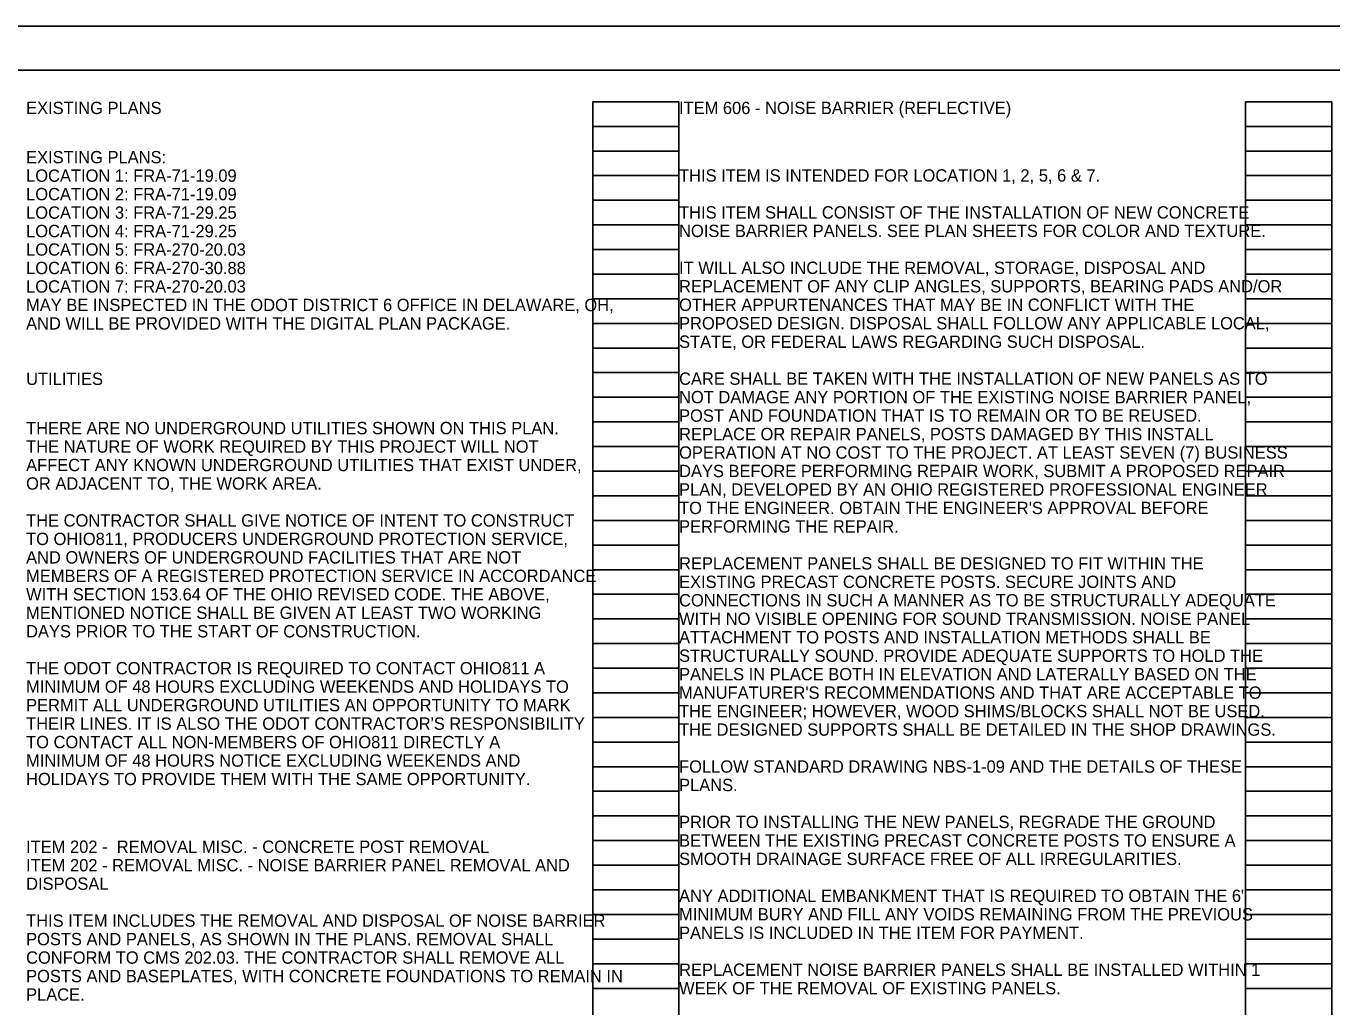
# Model space of a CAD drawing. Extents: x -10.6 to 34, y -3 to 22.
# Drawn here: x 9.82 to 24.66, y 10.85 to 22 of the extents above; entities that cross this region are included whole.
import ezdxf

# ---------------------------------------------------------------- set-up
doc = ezdxf.new("R2010")
doc.units = 0
for name, color, linetype in [('SH_Border', 7, 'Continuous'), ('SH_Cut_Line', 7, 'Continuous'), ('SH_Data', 7, 'Continuous'), ('SH_Text', 7, 'Continuous')]:
    doc.layers.add(name, color=color, linetype=linetype)

msp = doc.modelspace()

# ---------------------------------------------------------------- linework, layer by layer
at = {"layer": 'SH_Border'}
msp.add_lwpolyline([(1.5, 21.5), (33.5, 21.5), (33.5, 0.5), (1.5, 0.5)], close=True, dxfattribs=at)
at = {"layer": 'SH_Cut_Line'}
msp.add_lwpolyline([(0, 0), (34, 0), (34, 22), (0, 22)], close=True, dxfattribs=at)
at = {"layer": 'SH_Data'}
for p, q in [((16.26, 0.98), (16.26, 21.14)), ((16.26, 21.14), (17.24, 21.14)), ((17.24, 0.98), (17.24, 21.14)), ((23.68, 0.98), (23.68, 21.14)), ((23.68, 21.14), (24.66, 21.14)), ((24.66, 0.98), (24.66, 21.14)), ((16.26, 20.86), (17.24, 20.86)), ((23.68, 20.86), (24.66, 20.86)), ((16.26, 20.58), (17.24, 20.58)), ((23.68, 20.58), (24.66, 20.58)), ((16.26, 20.3), (17.24, 20.3)), ((23.68, 20.3), (24.66, 20.3)), ((16.26, 20.02), (17.24, 20.02)), ((23.68, 20.02), (24.66, 20.02)), ((16.26, 19.74), (17.24, 19.74)), ((23.68, 19.74), (24.66, 19.74)), ((16.26, 19.46), (17.24, 19.46)), ((23.68, 19.46), (24.66, 19.46)), ((16.26, 19.18), (17.24, 19.18)), ((23.68, 19.18), (24.66, 19.18)), ((16.26, 18.9), (17.24, 18.9)), ((23.68, 18.9), (24.66, 18.9)), ((16.26, 18.62), (17.24, 18.62)), ((23.68, 18.62), (24.66, 18.62)), ((16.26, 18.34), (17.24, 18.34)), ((23.68, 18.34), (24.66, 18.34)), ((16.26, 18.06), (17.24, 18.06)), ((23.68, 18.06), (24.66, 18.06)), ((16.26, 17.78), (17.24, 17.78)), ((23.68, 17.78), (24.66, 17.78)), ((16.26, 17.5), (17.24, 17.5)), ((23.68, 17.5), (24.66, 17.5)), ((16.26, 17.22), (17.24, 17.22)), ((23.68, 17.22), (24.66, 17.22)), ((16.26, 16.94), (17.24, 16.94)), ((23.68, 16.94), (24.66, 16.94)), ((16.26, 16.66), (17.24, 16.66)), ((23.68, 16.66), (24.66, 16.66)), ((16.26, 16.38), (17.24, 16.38)), ((23.68, 16.38), (24.66, 16.38)), ((16.26, 16.1), (17.24, 16.1)), ((23.68, 16.1), (24.66, 16.1)), ((16.26, 15.82), (17.24, 15.82)), ((23.68, 15.82), (24.66, 15.82)), ((16.26, 15.54), (17.24, 15.54)), ((23.68, 15.54), (24.66, 15.54)), ((16.26, 15.26), (17.24, 15.26)), ((23.68, 15.26), (24.66, 15.26)), ((16.26, 14.98), (17.24, 14.98)), ((23.68, 14.98), (24.66, 14.98)), ((16.26, 14.7), (17.24, 14.7)), ((23.68, 14.7), (24.66, 14.7)), ((16.26, 14.42), (17.24, 14.42)), ((23.68, 14.42), (24.66, 14.42)), ((16.26, 14.14), (17.24, 14.14)), ((23.68, 14.14), (24.66, 14.14)), ((16.26, 13.86), (17.24, 13.86)), ((23.68, 13.86), (24.66, 13.86)), ((16.26, 13.58), (17.24, 13.58)), ((23.68, 13.58), (24.66, 13.58)), ((16.26, 13.3), (17.24, 13.3)), ((23.68, 13.3), (24.66, 13.3)), ((16.26, 13.02), (17.24, 13.02)), ((23.68, 13.02), (24.66, 13.02)), ((16.26, 12.74), (17.24, 12.74)), ((23.68, 12.74), (24.66, 12.74)), ((16.26, 12.46), (17.24, 12.46)), ((23.68, 12.46), (24.66, 12.46)), ((16.26, 12.18), (17.24, 12.18)), ((23.68, 12.18), (24.66, 12.18)), ((16.26, 11.9), (17.24, 11.9)), ((23.68, 11.9), (24.66, 11.9)), ((16.26, 11.62), (17.24, 11.62)), ((23.68, 11.62), (24.66, 11.62)), ((16.26, 11.34), (17.24, 11.34)), ((23.68, 11.34), (24.66, 11.34)), ((16.26, 11.06), (17.24, 11.06)), ((23.68, 11.06), (24.66, 11.06))]:
    msp.add_line(p, q, dxfattribs=at)

# ---------------------------------------------------------------- texts
at = {"layer": 'SH_Text'}
for s, p in [('EXISTING PLANS', (9.82, 21)), ('ITEM 606 - NOISE BARRIER (REFLECTIVE)', (17.24, 21)), ('EXISTING PLANS:', (9.82, 20.44)), ('LOCATION 1: FRA-71-19.09', (9.82, 20.23)), ('THIS ITEM IS INTENDED FOR LOCATION 1, 2, 5, 6 & 7.', (17.241, 20.232)), ('LOCATION 2: FRA-71-19.09', (9.82, 20.02)), ('LOCATION 3: FRA-71-29.25', (9.82, 19.81)), ('THIS ITEM SHALL CONSIST OF THE INSTALLATION OF NEW CONCRETE ', (17.241, 19.812)), ('LOCATION 4: FRA-71-29.25', (9.82, 19.6)), ('NOISE BARRIER PANELS. SEE PLAN SHEETS FOR COLOR AND TEXTURE.', (17.241, 19.602)), ('LOCATION 5: FRA-270-20.03', (9.82, 19.39)), ('LOCATION 6: FRA-270-30.88', (9.82, 19.18)), ('IT WILL ALSO INCLUDE THE REMOVAL, STORAGE, DISPOSAL AND ', (17.241, 19.182)), ('LOCATION 7: FRA-270-20.03', (9.82, 18.97)), ('REPLACEMENT OF ANY CLIP ANGLES, SUPPORTS, BEARING PADS AND/OR ', (17.241, 18.972)), ('MAY BE INSPECTED IN THE ODOT DISTRICT 6 OFFICE IN DELAWARE, OH, ', (9.82, 18.76)), ('OTHER APPURTENANCES THAT MAY BE IN CONFLICT WITH THE ', (17.241, 18.762)), ('AND WILL BE PROVIDED WITH THE DIGITAL PLAN PACKAGE.', (9.82, 18.55)), ('PROPOSED DESIGN. DISPOSAL SHALL FOLLOW ANY APPLICABLE LOCAL, ', (17.241, 18.552)), ('STATE, OR FEDERAL LAWS REGARDING SUCH DISPOSAL.', (17.241, 18.342)), ('UTILITIES', (9.82, 17.92)), ('CARE SHALL BE TAKEN WITH THE INSTALLATION OF NEW PANELS AS TO ', (17.241, 17.922)), ('NOT DAMAGE ANY PORTION OF THE EXISTING NOISE BARRIER PANEL, ', (17.241, 17.712)), ('POST AND FOUNDATION THAT IS TO REMAIN OR TO BE REUSED. ', (17.241, 17.502)), ('THERE ARE NO UNDERGROUND UTILITIES SHOWN ON THIS PLAN. ', (9.82, 17.36)), ('REPLACE OR REPAIR PANELS, POSTS DAMAGED BY THIS INSTALL ', (17.241, 17.292)), ('THE NATURE OF WORK REQUIRED BY THIS PROJECT WILL NOT ', (9.82, 17.15)), ('OPERATION AT NO COST TO THE PROJECT. AT LEAST SEVEN (7) BUSINESS ', (17.241, 17.082)), ('AFFECT ANY KNOWN UNDERGROUND UTILITIES THAT EXIST UNDER, ', (9.82, 16.94)), ('DAYS BEFORE PERFORMING REPAIR WORK, SUBMIT A PROPOSED REPAIR ', (17.241, 16.872)), ('OR ADJACENT TO, THE WORK AREA.', (9.82, 16.73)), ('PLAN, DEVELOPED BY AN OHIO REGISTERED PROFESSIONAL ENGINEER ', (17.241, 16.662)), ("TO THE ENGINEER. OBTAIN THE ENGINEER'S APPROVAL BEFORE ", (17.241, 16.452)), ('THE CONTRACTOR SHALL GIVE NOTICE OF INTENT TO CONSTRUCT ', (9.82, 16.31)), ('PERFORMING THE REPAIR.', (17.241, 16.242)), ('TO OHIO811, PRODUCERS UNDERGROUND PROTECTION SERVICE, ', (9.82, 16.1)), ('AND OWNERS OF UNDERGROUND FACILITIES THAT ARE NOT ', (9.82, 15.89)), ('REPLACEMENT PANELS SHALL BE DESIGNED TO FIT WITHIN THE ', (17.241, 15.822)), ('MEMBERS OF A REGISTERED PROTECTION SERVICE IN ACCORDANCE ', (9.82, 15.68)), ('EXISTING PRECAST CONCRETE POSTS. SECURE JOINTS AND ', (17.241, 15.612)), ('WITH SECTION 153.64 OF THE OHIO REVISED CODE. THE ABOVE, ', (9.82, 15.47)), ('CONNECTIONS IN SUCH A MANNER AS TO BE STRUCTURALLY ADEQUATE ', (17.241, 15.402)), ('MENTIONED NOTICE SHALL BE GIVEN AT LEAST TWO WORKING ', (9.82, 15.26)), ('WITH NO VISIBLE OPENING FOR SOUND TRANSMISSION. NOISE PANEL ', (17.241, 15.192)), ('DAYS PRIOR TO THE START OF CONSTRUCTION.', (9.82, 15.05)), ('ATTACHMENT TO POSTS AND INSTALLATION METHODS SHALL BE ', (17.241, 14.982)), ('STRUCTURALLY SOUND. PROVIDE ADEQUATE SUPPORTS TO HOLD THE ', (17.241, 14.772)), ('THE ODOT CONTRACTOR IS REQUIRED TO CONTACT OHIO811 A ', (9.82, 14.63)), ('PANELS IN PLACE BOTH IN ELEVATION AND LATERALLY BASED ON THE ', (17.241, 14.562)), ('MINIMUM OF 48 HOURS EXCLUDING WEEKENDS AND HOLIDAYS TO ', (9.82, 14.42)), ("MANUFATURER'S RECOMMENDATIONS AND THAT ARE ACCEPTABLE TO ", (17.241, 14.352)), ('PERMIT ALL UNDERGROUND UTILITIES AN OPPORTUNITY TO MARK ', (9.82, 14.21)), ('THE ENGINEER; HOWEVER, WOOD SHIMS/BLOCKS SHALL NOT BE USED. ', (17.241, 14.142)), ("THEIR LINES. IT IS ALSO THE ODOT CONTRACTOR'S RESPONSIBILITY ", (9.82, 14)), ('THE DESIGNED SUPPORTS SHALL BE DETAILED IN THE SHOP DRAWINGS.', (17.241, 13.932)), ('TO CONTACT ALL NON-MEMBERS OF OHIO811 DIRECTLY A ', (9.82, 13.79)), ('MINIMUM OF 48 HOURS NOTICE EXCLUDING WEEKENDS AND ', (9.82, 13.58)), ('FOLLOW STANDARD DRAWING NBS-1-09 AND THE DETAILS OF THESE ', (17.241, 13.512)), ('HOLIDAYS TO PROVIDE THEM WITH THE SAME OPPORTUNITY.', (9.82, 13.37)), ('PLANS.', (17.241, 13.302)), ('PRIOR TO INSTALLING THE NEW PANELS, REGRADE THE GROUND ', (17.241, 12.882)), ('BETWEEN THE EXISTING PRECAST CONCRETE POSTS TO ENSURE A ', (17.241, 12.672)), ('ITEM 202 -  REMOVAL MISC. - CONCRETE POST REMOVAL', (9.82, 12.6)), ('ITEM 202 - REMOVAL MISC. - NOISE BARRIER PANEL REMOVAL AND ', (9.82, 12.39)), ('SMOOTH DRAINAGE SURFACE FREE OF ALL IRREGULARITIES.', (17.241, 12.462)), ('DISPOSAL', (9.82, 12.18)), ('ANY ADDITIONAL EMBANKMENT THAT IS REQUIRED TO OBTAIN THE 6" ', (17.241, 12.042)), ('THIS ITEM INCLUDES THE REMOVAL AND DISPOSAL OF NOISE BARRIER ', (9.82, 11.76)), ('MINIMUM BURY AND FILL ANY VOIDS REMAINING FROM THE PREVIOUS ', (17.241, 11.832)), ('PANELS IS INCLUDED IN THE ITEM FOR PAYMENT.', (17.241, 11.622)), ('POSTS AND PANELS, AS SHOWN IN THE PLANS. REMOVAL SHALL ', (9.82, 11.55)), ('CONFORM TO CMS 202.03. THE CONTRACTOR SHALL REMOVE ALL ', (9.82, 11.34)), ('REPLACEMENT NOISE BARRIER PANELS SHALL BE INSTALLED WITHIN 1 ', (17.241, 11.202)), ('POSTS AND BASEPLATES, WITH CONCRETE FOUNDATIONS TO REMAIN IN ', (9.82, 11.13)), ('WEEK OF THE REMOVAL OF EXISTING PANELS.', (17.241, 10.992)), ('PLACE.', (9.82, 10.92))]:
    msp.add_text(s, height=0.14, dxfattribs=at).set_placement(p)

doc.saveas('drawing.dxf')
